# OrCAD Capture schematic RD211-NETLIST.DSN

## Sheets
1 2: size Custom
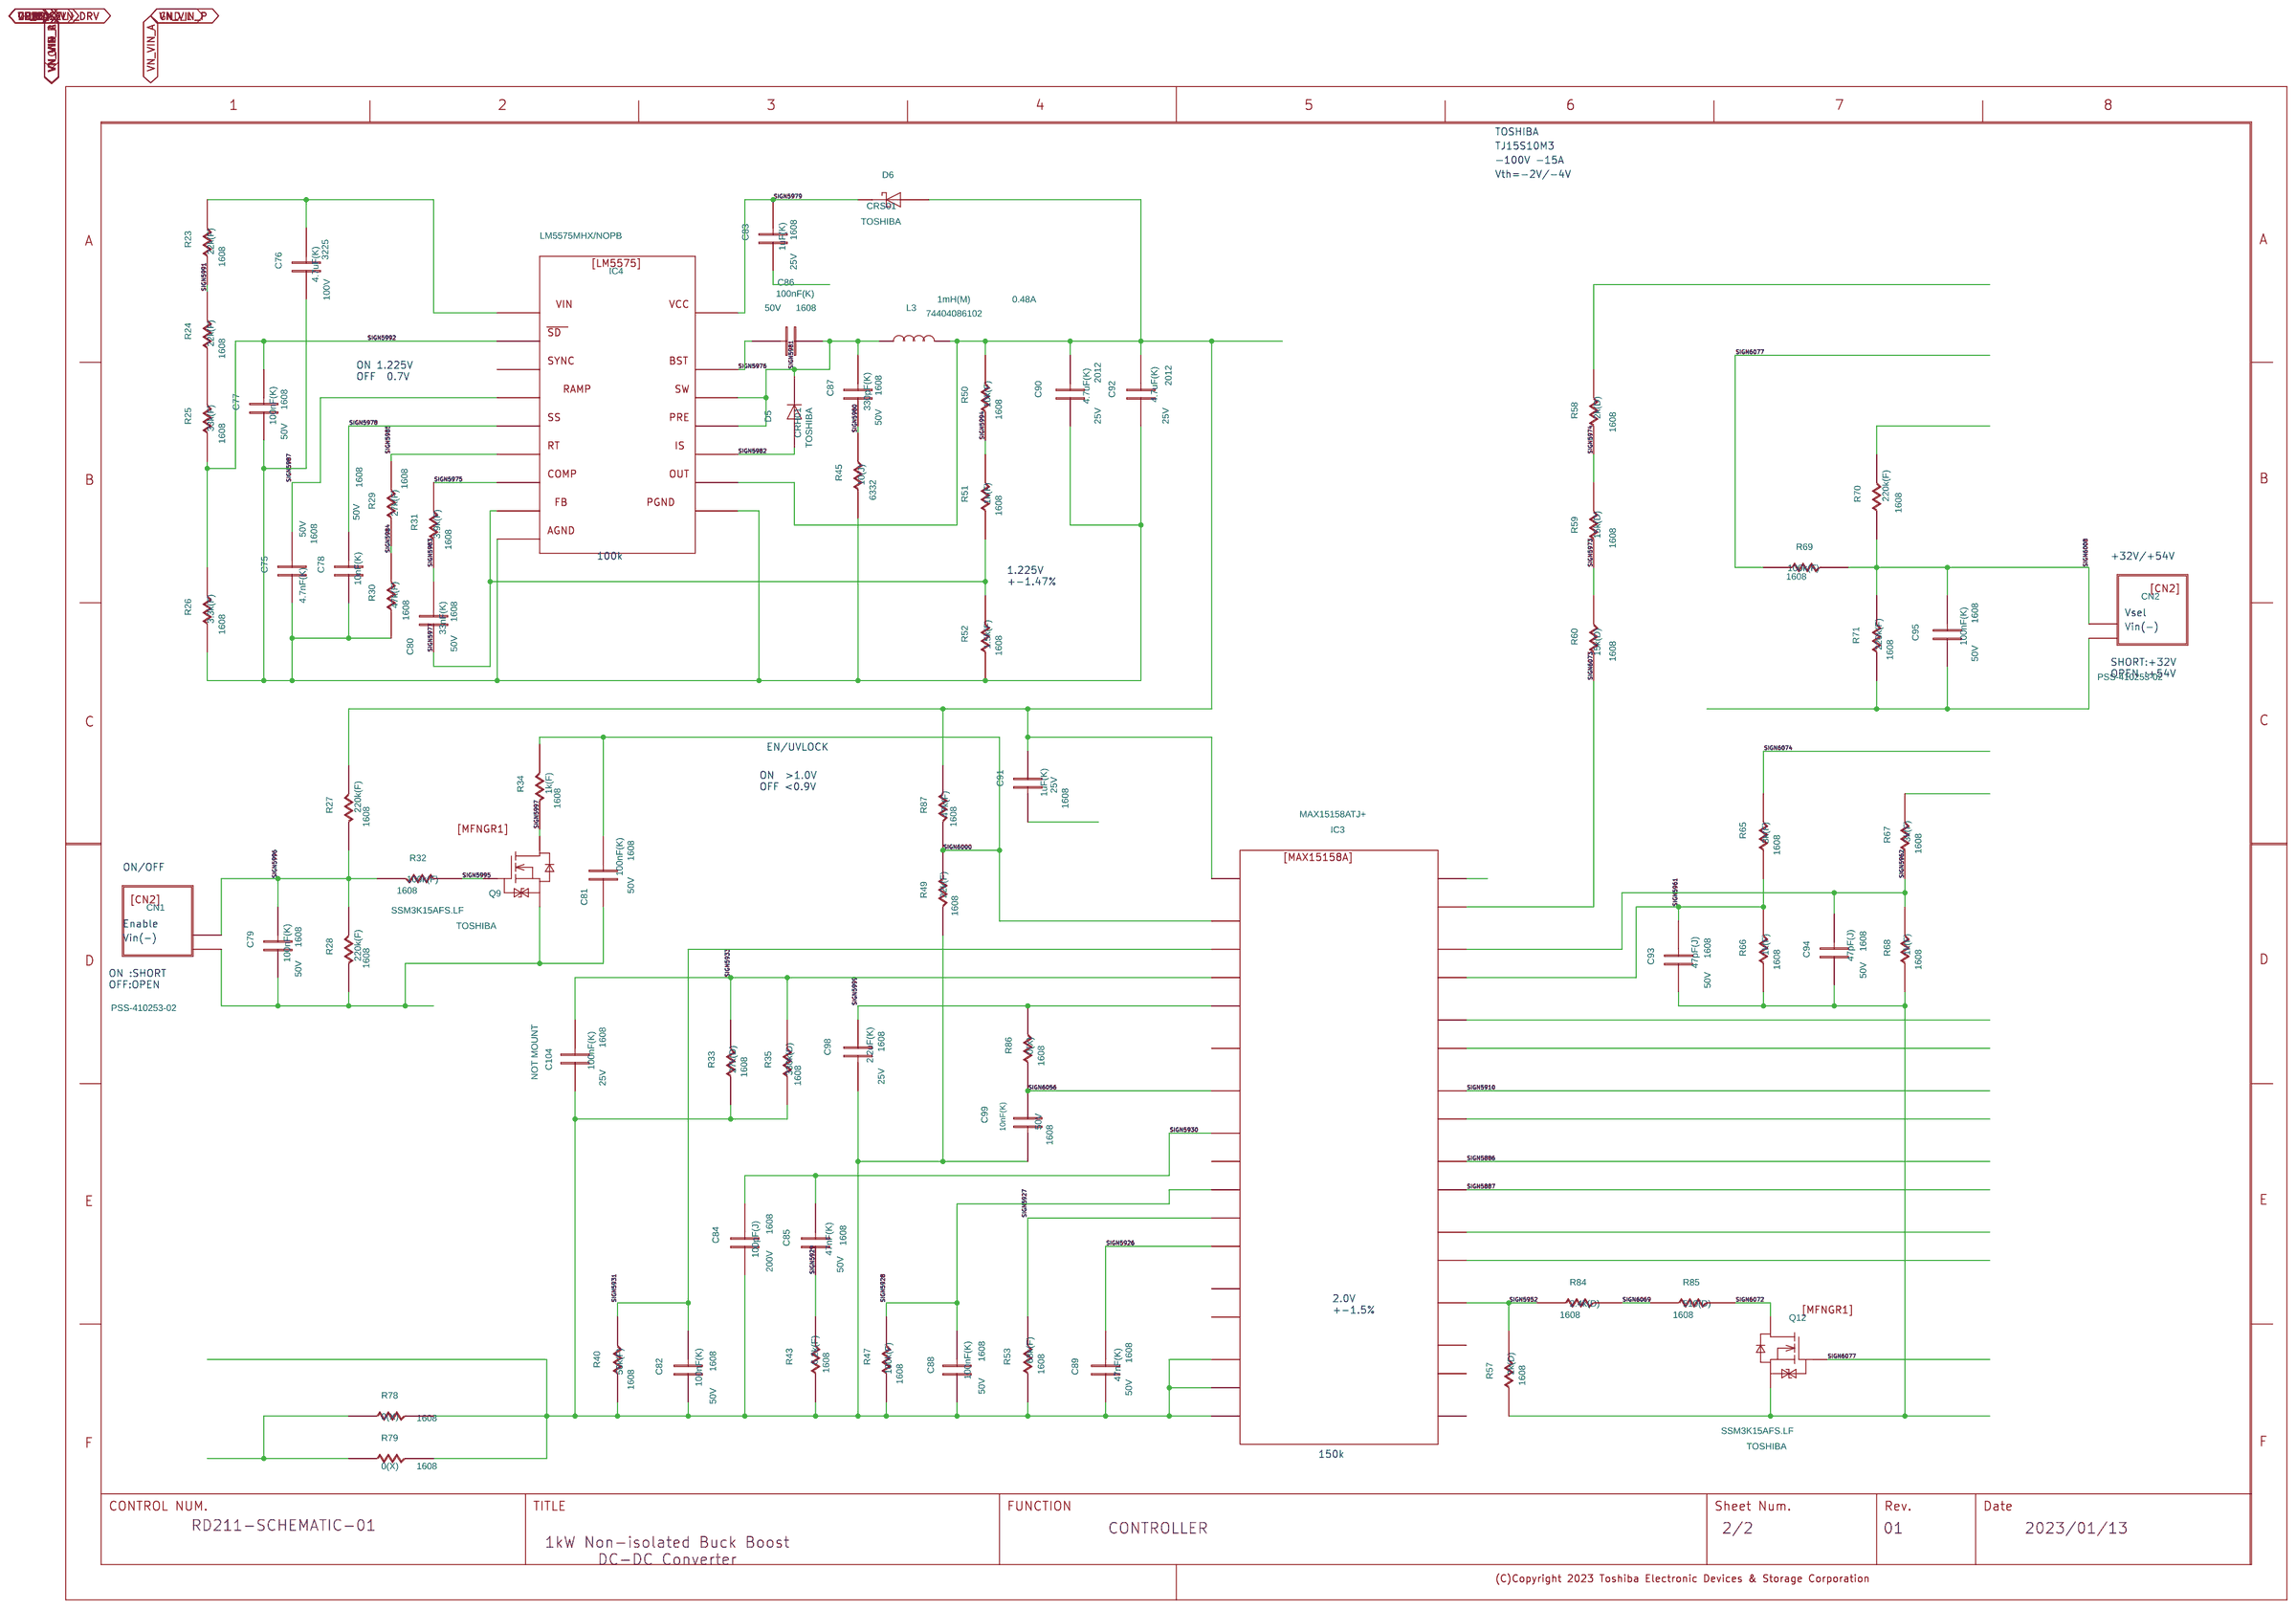
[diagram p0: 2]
2 1: size Custom
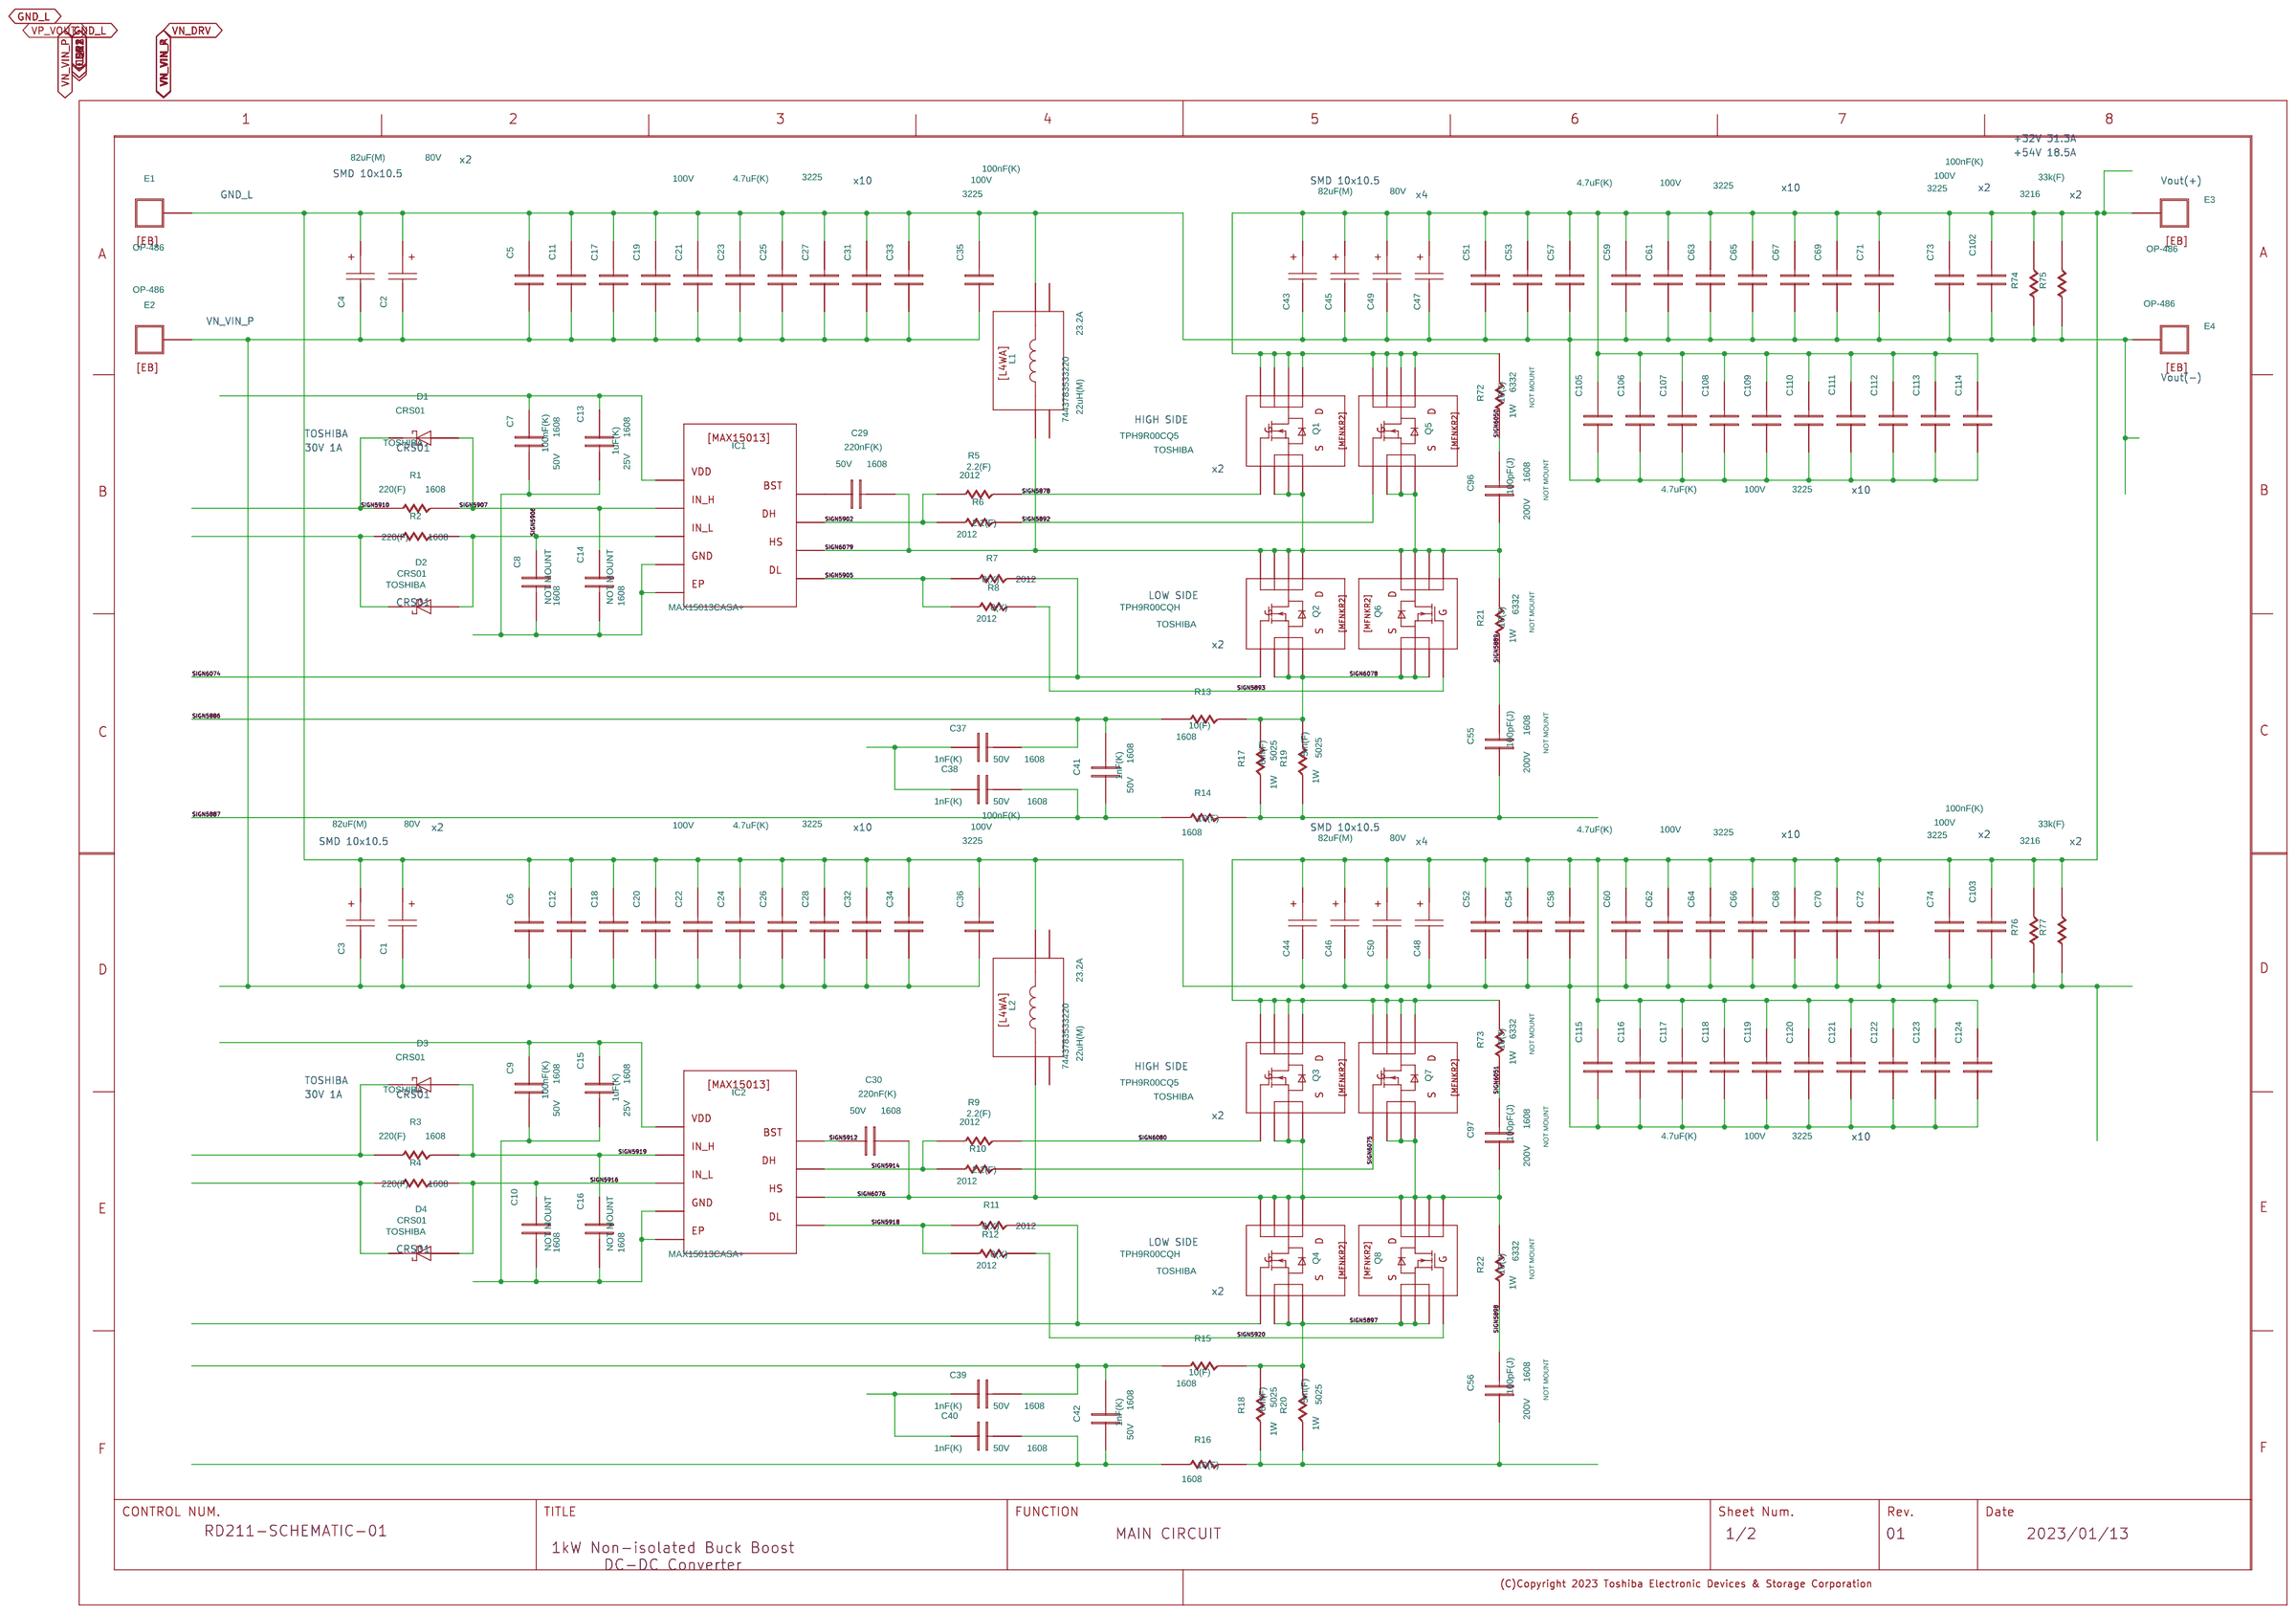
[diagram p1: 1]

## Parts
sheet 1
C1  CP
C2  CP
C3  CP
C4  CP
C5  C
C6  C
C7  C
C8  C
C9  C
C10  C
C11  C
C12  C
C13  C
C14  C
C15  C
C16  C
C17  C
C18  C
C19  C
C20  C
C21  C
C22  C
C23  C
C24  C
C25  C
C26  C
C27  C
C28  C
C29  C
C30  C
C31  C
C32  C
C33  C
C34  C
C35  C
C36  C
C37  C
C38  C
C39  C
C40  C
C41  C
C42  C
C43  CP
C44  CP
C45  CP
C46  CP
C47  CP
C48  CP
C49  CP
C50  CP
C51  C
C52  C
C53  C
C54  C
C55  C
C56  C
C57  C
C58  C
C59  C
C60  C
C61  C
C62  C
C63  C
C64  C
C65  C
C66  C
C67  C
C68  C
C69  C
C70  C
C71  C
C72  C
C73  C
C74  C
C96  C
C97  C
C102  C
C103  C
C105  C
C106  C
C107  C
C108  C
C109  C
C110  C
C111  C
C112  C
C113  C
C114  C
C115  C
C116  C
C117  C
C118  C
C119  C
C120  C
C121  C
C122  C
C123  C
C124  C
D1  SBD
D2  SBD
D3  SBD
D4  SBD
E1  EB
E2  EB
E3  EB
E4  EB
IC1  MAX15013
IC2  MAX15013
L1  L4WA
L2  L4WA
Q1  MFNKR2
Q2  MFNKR2
Q3  MFNKR2
Q4  MFNKR2
Q5  MFNKR2
Q6  MFNKR2
Q7  MFNKR2
Q8  MFNKR2
R1  R
R2  R
R3  R
R4  R
R5  R
R6  R
R7  R
R8  R
R9  R
R10  R
R11  R
R12  R
R13  R
R14  R
R15  R
R16  R
R17  R
R18  R
R19  R
R20  R
R21  R
R22  R
R72  R
R73  R
R74  R
R75  R
R76  R
R77  R
U?#1  WAKU_DEF100
sheet 2
C75  C
C76  C
C77  C
C78  C
C79  C
C80  C
C81  C
C82  C
C83  C
C84  C
C85  C
C86  C
C87  C
C88  C
C89  C
C90  C
C91  C
C92  C
C93  C
C94  C
C95  C
C98  C
C99  C
C104  C
CN1  CN2
CN2  CN2
D5  D
D6  SBD
IC3  MAX15158A
IC4  LM5575
L3  L
Q9  MFNGR1
Q12  MFNGR1
R23  R
R24  R
R25  R
R26  R
R27  R
R28  R
R29  R
R30  R
R31  R
R32  R
R33  R
R34  R
R35  R
R40  R
R43  R
R45  R
R47  R
R49  R
R50  R
R51  R
R52  R
R53  R
R57  R
R58  R
R59  R
R60  R
R65  R
R66  R
R67  R
R68  R
R69  R
R70  R
R71  R
R78  R
R79  R
R84  R
R85  R
R86  R
R87  R
U?#2  WAKU_DEF100

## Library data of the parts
C1-C4 C43-C50 = CP: CAPACITANCETOLE: M; CDMASTERCADCELG: DC845R; COMP: G36030155199; COMPONENTNAME: G36030155199_package; FNCLASSCODEG: P03-01; FNPARTSCODEG: C; FNPARTSNAMEG: CHIP ALUMINUM ELECTROLYTIC CAPACITOR; FUNCN: G36030155199; GCOUNT: 1; ICX_PART_MODEL: CON_470u; MAXGCOUNT: 1; MFFORMINGDIVP: KD; MFMOUNTSYMBOLP: 80; MFPACKAGEMETHOP: S; MFSOLDERINGPROP: F; NOMINALCAPACITA: 470u; OUMECLASSIFICATION: ƒAƒ‹ƒ~“d‰ðƒRƒ“ƒfƒ“ƒT; OUMEMAKER: NAE ¼ºdqi; OUMEMAKERKATAMEI: EEVHB1A471P; OUMEPARTTYPE: C; PCODE: P03090017118; QUADMODEL: CON_470u; RATEDVOLTAGE: 10; SIZECODESMD: 1010; SQ_PART_MODEL: CON_470u; VAL1: 82uF(M); VAL2: 80V
C5 C6 C11 C12 C17-C28 C31-C34 C51-C54 C57-C72 C105-C124 = C: CAPACITANCETOLE: J; CDMASTERCADCELG: C8101B; COMP: G36030013017; COMPONENTNAME: G36030013017_package; FNCLASSCODEG: P03-05; FNPARTSNAMEG: CHIP M-PEN FILM CAPACITOR; FUNCN: G36030013017; GCOUNT: 1; ICX_PART_MODEL: CON_100n; MAXGCOUNT: 1; MFFORMINGDIVP: KC; MFMOUNTSYMBOLP: 80; MFPACKAGEMETHOP: S; MFSOLDERINGPROP: .; NOMINALCAPACITA: 100n; OUMECLASSIFICATION: ƒtƒBƒ‹ƒƒRƒ“ƒfƒ“ƒT; OUMEMAKER: NAT ¼ºdíYÆ; OUMEMAKERKATAMEI: ECWU1C104JB5; PCODE: P03102001111; QUADMODEL: CON_100n; RATEDVOLTAGE: 16; SIZECODESMD: 3225; SQ_PART_MODEL: CON_100n; VAL1: 4.7uF(K); VAL2: 100V
C7 C9 = C: CAPACITANCETOLE: K; CDMASTERCADCELG: KC0008; COMP: GDM030001137; COMPONENTNAME: GDM030001137_package; FNCLASSCODEG: P03-03; FNPARTSNAMEG: CHIP CERAMIC CAPACITOR (1608); FUNCN: GDM030001137; GCOUNT: 1; ICX_PART_MODEL: CON_100n; MAXGCOUNT: 1; MFFORMINGDIVP: KC; MFMOUNTSYMBOLP: 80; MFPACKAGEMETHOP: S; MFSOLDERINGPROP: .; NOMINALCAPACITA: 100n; OUMECLASSIFICATION: ƒZƒ‰ƒ~ƒbƒNƒRƒ“ƒfƒ“ƒT; OUMEMAKER: MRT ºc»ì; OUMEMAKERKATAMEI: GRM188B31H104KA92D; PARTCOMMENT: ã\Z<KC0008> ªtbgvgÉo^³êÄ¢Ü¹ñB; PCODE: P03B000001KW; QUADMODEL: CON_100n; RATEDVOLTAGE: 50; SIZECODESMD: 1608; SQ_PART_MODEL: CON_100n; TEMPCHARACTERI2: B; VAL1: 100nF(K); VAL2: 50V
C8 C10 C14 C16 = C: CAPACITANCETOLE: J; CDMASTERCADCELG: C8100E; COMP: GDM030000578; COMPONENTNAME: GDM030000578_package; FNCLASSCODEG: P03-03; FNPARTSNAMEG: CHIP CERAMIC CAPACITOR (1608); FUNCN: GDM030000578; GCOUNT: 1; ICX_PART_MODEL: CON_220p; MAXGCOUNT: 1; MFFORMINGDIVP: KC; MFMOUNTSYMBOLP: 80; MFPACKAGEMETHOP: S; MFSOLDERINGPROP: .; NOMINALCAPACITA: 220p; NOTMOUNT: NOT MOUNT; OUMECLASSIFICATION: ƒZƒ‰ƒ~ƒbƒNƒRƒ“ƒfƒ“ƒT; OUMEMAKER: KYC ‹žƒZƒ‰; OUMEMAKERKATAMEI: CM105CH221J50AT; PCODE: P03039269127; QUADMODEL: CON_220p; RATEDVOLTAGE: 50; SIZECODESMD: 1608; SQ_PART_MODEL: CON_220p; TEMPCHARACTERI2: CH; VAL1: 220pF(J); VAL2: 50V
C13 C15 C91 = C: CAPACITANCETOLE: K; CDMASTERCADCELG: KC0008; COMP: GDM030000346; COMPONENTNAME: GDM030000346_package; FNCLASSCODEG: P03-03; FNPARTSNAMEG: CHIP CERAMIC CAPACITOR (1608); FUNCN: GDM030000346; GCOUNT: 1; ICX_PART_MODEL: CON_1u; MAXGCOUNT: 1; MFFORMINGDIVP: KC; MFMOUNTSYMBOLP: 80; MFPACKAGEMETHOP: S; MFSOLDERINGPROP: .; NOMINALCAPACITA: 1u; OUMECLASSIFICATION: ƒZƒ‰ƒ~ƒbƒNƒRƒ“ƒfƒ“ƒT; OUMEMAKER: KYC ‹žƒZƒ‰; OUMEMAKERKATAMEI: CV105B105K25AT; PARTCOMMENT: ã\Z<KC0008> ªtbgvgÉo^³êÄ¢Ü¹ñB; PCODE: P03B0000016L; QUADMODEL: CON_1u; RATEDVOLTAGE: 25; SIZECODESMD: 1608; SQ_PART_MODEL: CON_1u; TEMPCHARACTERI2: B; VAL1: 1uF(K); VAL2: 25V
C29 C30 = C: CAPACITANCETOLE: K; CDMASTERCADCELG: KC0008; COMP: GDM030001014; COMPONENTNAME: GDM030001014_package; FNCLASSCODEG: P03-03; FNPARTSNAMEG: CHIP CERAMIC CAPACITOR (1608); FUNCN: GDM030001014; GCOUNT: 1; ICX_PART_MODEL: CON_220n; MAXGCOUNT: 1; MFFORMINGDIVP: KC; MFMOUNTSYMBOLP: 80; MFPACKAGEMETHOP: S; MFSOLDERINGPROP: .; NOMINALCAPACITA: 220n; OUMECLASSIFICATION: ƒZƒ‰ƒ~ƒbƒNƒRƒ“ƒfƒ“ƒT; OUMEMAKER: MRT ºc»ì; OUMEMAKERKATAMEI: GRM188B11C224KA01D; PARTCOMMENT: ã\Z<KC0008> ªtbgvgÉo^³êÄ¢Ü¹ñB; PCODE: P03B000001L3; QUADMODEL: CON_220n; RATEDVOLTAGE: 16; SIZECODESMD: 1608; SQ_PART_MODEL: CON_220n; TEMPCHARACTERI2: B; VAL1: 220nF(K); VAL2: 50V
C35 C36 C73 C74 C102 C103 = C: CAPACITANCETOLE: J; CDMASTERCADCELG: C8101B; COMP: G36030013017; COMPONENTNAME: G36030013017_package; FNCLASSCODEG: P03-05; FNPARTSNAMEG: CHIP M-PEN FILM CAPACITOR; FUNCN: G36030013017; GCOUNT: 1; ICX_PART_MODEL: CON_100n; MAXGCOUNT: 1; MFFORMINGDIVP: KC; MFMOUNTSYMBOLP: 80; MFPACKAGEMETHOP: S; MFSOLDERINGPROP: .; NOMINALCAPACITA: 100n; OUMECLASSIFICATION: ƒtƒBƒ‹ƒƒRƒ“ƒfƒ“ƒT; OUMEMAKER: NAT ¼ºdíYÆ; OUMEMAKERKATAMEI: ECWU1C104JB5; PCODE: P03102001111; QUADMODEL: CON_100n; RATEDVOLTAGE: 16; SIZECODESMD: 3225; SQ_PART_MODEL: CON_100n; VAL1: 100nF(K); VAL2: 100V
C37-C42 = C: ASIMVALUE: 1N; CAPACITANCETOLE: K; CDMASTERCADCELG: C8100E; COMP: G36030011044; COMPONENTNAME: G36030011044_package; FNCLASSCODEG: P03-03; FNPARTSNAMEG: CHIP CERAMIC CAPACITOR (1608); FUNCN: G36030011044; GCOUNT: 1; ICX_PART_MODEL: CON_1n; MAXGCOUNT: 1; MFFORMINGDIVP: KC; MFMOUNTSYMBOLP: 80; MFPACKAGEMETHOP: S; MFSOLDERINGPROP: .; NOMINALCAPACITA: 1n; OUMECLASSIFICATION: ƒZƒ‰ƒ~ƒbƒNƒRƒ“ƒfƒ“ƒT; OUMEMAKER: MRT ºc»ì; OUMEMAKERKATAMEI: GRM39B102K50PT; PCODE: P03039045226; QUADMODEL: CON_1n; RATEDVOLTAGE: 50; SIZECODESMD: 1608; SQ_PART_MODEL: CON_1n; TEMPCHARACTERI2: B; TOLERANCE: K; VAL1: 1nF(K); VAL2: 50V
C55 C56 = C: CAPACITANCETOLE: J; CDMASTERCADCELG: C8100E; COMP: G36030011365; FNCLASSCODEG: P03-03; FNPARTSNAMEG: CHIP CERAMIC CAPACITOR (1608); GCOUNT: 1; MAXGCOUNT: 1; MFFORMINGDIVP: KC; MFMOUNTSYMBOLP: 80; MFPACKAGEMETHOP: S; MFSOLDERINGPROP: .; NOMINALCAPACITA: 100p; NOTMOUNT: NOT MOUNT; OUMECLASSIFICATION: ƒZƒ‰ƒ~ƒbƒNƒRƒ“ƒfƒ“ƒT; OUMEMAKER: KYC ‹žƒZƒ‰; OUMEMAKERKATAMEI: CM105CH101J50AT; PCODE: P03039177125; QUADMODEL: CON_100p; RATEDVOLTAGE: 50; SIZECODESMD: 1608; TEMPCHARACTERI2: CH; TOLERANCE: J; VAL1: 100pF(J); VAL2: 200V
C96 C97 = C: ASIMVALUE: 100P; CAPACITANCETOLE: J; CDMASTERCADCELG: C8100E; COMP: G36030011365; COMPONENTNAME: G36030011365_package; FNCLASSCODEG: P03-03; FNPARTSNAMEG: CHIP CERAMIC CAPACITOR (1608); FUNCN: G36030011365; GCOUNT: 1; ICX_PART_MODEL: CON_100p; MAXGCOUNT: 1; MFFORMINGDIVP: KC; MFMOUNTSYMBOLP: 80; MFPACKAGEMETHOP: S; MFSOLDERINGPROP: .; NOMINALCAPACITA: 100p; NOTMOUNT: NOT MOUNT; OUMECLASSIFICATION: ƒZƒ‰ƒ~ƒbƒNƒRƒ“ƒfƒ“ƒT; OUMEMAKER: KYC ‹žƒZƒ‰; OUMEMAKERKATAMEI: CM105CH101J50AT; PCODE: P03039177125; QUADMODEL: CON_100p; RATEDVOLTAGE: 50; SIZECODESMD: 1608; SQ_PART_MODEL: CON_100p; TEMPCHARACTERI2: CH; TOLERANCE: J; VAL1: 100pF(J); VAL2: 200V
D1-D4 D6 = SBD: CDMASTERCADCELG: DD831R; COMP: G36420146011; COMPONENTNAME: G36420146011_package; FNCLASSCODEG: P42-03; FNPARTSCODEG: D; FNPARTSNAMEG: SCHOTTKY BARRIER DIODE; FORWARDVOLTAGEM: 0; FUNCN: G36420146011; GCOUNT: 1; MAXAVERAGEFORWA: 1; MAXGCOUNT: 1; MAXREPETITIVEPE: 30; MAXREVERSEVOLTA: 0; MFFORMINGDIVP: MM; MFMOUNTSYMBOLP: 80; MFPACKAGEMETHOP: S; MFSOLDERINGPROP: .; MOUNTINGFORMSMD: SMD; OUMECLASSIFICATION: êÊ®¬fq; OUMEMAKER: TSB Åixorrj; OUMEMAKERKATAMEI: CRS01(TE85L); OUMEPARTTYPE: D; PCODE: P42471001117; PEAKFORWARDVOLT: 360m; QUADMODEL: dummymodel; REVERSECURRENT: 0; USERCOMPTEXT3: TOSHIBA; VAL1: CRS01; VAL3: CRS01; ZENERVOLTAGEMAX: 0; ZENERVOLTAGEMIN: 0
E1-E4 = EB: COMP: OP-486; COMPONENTNAME: pinass:EB_func:EB; GCOUNT: 1; MAXGCOUNT: 1; OUMEMAKER: ƒIƒTƒ_; OUMEMAKERKATAMEI: OP-486; VAL1: OP-486; VAL3: OP-486
IC1 IC2 = MAX15013: COMP: MAX15013CASA+; COMPONENTNAME: pinass:MAX15013_func:MAX15013; GCOUNT: 1; MAXGCOUNT: 1; OUMEMAKER: Maxim Integrated; OUMEMAKERKATAMEI: MAX15013CASA+; VAL1: MAX15013CASA+; VAL3: MAX15013CASA+
L1 L2 = L4WA: COMP: 7443783533220; COMPONENTNAME: L4WA.L4WA; GCOUNT: 1; MAXGCOUNT: 1; OUMEMAKER: WURTH; OUMEMAKERKATAMEI: 7443783533330; VAL1: 22uH(M); VAL2: 23.2A; VAL3: 7443783533220
Q1 Q3 Q5 Q7 = MFNKR2: COMP: TPH6R003NL; COMPONENTNAME: MFNKR2_MFNKR2; GCOUNT: 1; MAXGCOUNT: 1; OUMEMAKER: TOSHIBA; OUMEMAKERKATAMEI: TPH6R003NL; USERCOMPTEXT3: TOSHIBA; VAL1: TPH9R00CQ5; VAL3: TPH9R00CQ5
Q2 Q4 = MFNKR2: COMP: TPH6R003NL; COMPONENTNAME: MFNKR2_MFNKR2; GCOUNT: 1; MAXGCOUNT: 1; OUMEMAKER: TOSHIBA; OUMEMAKERKATAMEI: TPH6R003NL; USERCOMPTEXT3: TOSHIBA; VAL1: TPH9R00CQH; VAL3: TPH9R00CQH
Q6 Q8 = MFNKR2: COMP: TPH6R003NL; GCOUNT: 1; MAXGCOUNT: 1; OUMEMAKER: TOSHIBA; OUMEMAKERKATAMEI: TPH6R003NL; USERCOMPTEXT3: TOSHIBA; VAL1: TPH9R00CQH; VAL3: TPH9R00CQH
R1-R4 = R: ASIMVALUE: 220; CDMASTERCADCELG: DR802R; COMP: G36010027393; COMPONENTNAME: G36010027393_package; FNCLASSCODEG: P01-08; FNPARTSNAMEG: CHIP RESISTOR (1608); FUNCN: G36010027393; GCOUNT: 1; ICX_PART_MODEL: RES_220; MAXGCOUNT: 1; MFFORMINGDIVP: KC; MFMOUNTSYMBOLP: 80; MFPACKAGEMETHOP: S; MFSOLDERINGPROP: .; MOUNTINGFORMSMD: SMD; NOMINALRESISTAN: 220; NUMBEROFELEMENT: 0; OUMECLASSIFICATION: \ÊÀpÅèïRí; OUMEMAKER: NAE ¼ºdqi; OUMEMAKERKATAMEI: ERJ3GEYF221V; PCODE: P01042198625; POWERRATING: 63m; QUADMODEL: RES_220; RESISTANCETOLER: F; SIZECODESMD: 1608; SQ_PART_MODEL: RES_220; TOLERANCE: F; VAL1: 220(F); VAL2: 62.5mW
R5 R6 R9 R10 = R: CDMASTERCADCELG: DR910A; COMP: G36010106012; COMPONENTNAME: G36010106012_package; FNCLASSCODEG: P01-08; FNPARTSNAMEG: CHIP RESISTOR (2012); FUNCN: G36010106012; GCOUNT: 1; ICX_PART_MODEL: RES_2.2; MAXGCOUNT: 1; MFFORMINGDIVP: KC; MFMOUNTSYMBOLP: 90; MFPACKAGEMETHOP: S; MFSOLDERINGPROP: .; MOUNTINGFORMSMD: SMD; NOMINALRESISTAN: 2.2; NUMBEROFELEMENT: 0; OUMECLASSIFICATION: \ÊÀpÅèïRí; OUMEMAKER: NAE ¼ºdqi; OUMEMAKERKATAMEI: ERJ6RQF2R2V; PCODE: P01048019214; POWERRATING: 250m; QUADMODEL: RES_2.2; RESISTANCETOLER: F; SIZECODESMD: 2012; SQ_PART_MODEL: RES_2.2; VAL1: 2.2(F); VAL2: 250mW
R7 R8 R11 R12 = R: CDMASTERCADCELG: DR910A; COMP: G36010106081; COMPONENTNAME: G36010106081_package; FNCLASSCODEG: P01-08; FNPARTSNAMEG: CHIP RESISTOR (2012); FUNCN: G36010106081; GCOUNT: 1; ICX_PART_MODEL: RES_1; MAXGCOUNT: 1; MFFORMINGDIVP: KC; MFMOUNTSYMBOLP: 90; MFPACKAGEMETHOP: S; MFSOLDERINGPROP: .; MOUNTINGFORMSMD: SMD; NOMINALRESISTAN: 1; NUMBEROFELEMENT: 0; OUMECLASSIFICATION: \ÊÀpÅèïRí; OUMEMAKER: NAE ¼ºdqi; OUMEMAKERKATAMEI: ERJ6RQF1R0V; PCODE: P01048017210; POWERRATING: 250m; QUADMODEL: RES_1; RESISTANCETOLER: F; SIZECODESMD: 2012; SQ_PART_MODEL: RES_1; VAL1: 0(X)
R13-R16 = R: ASIMVALUE: 10; CDMASTERCADCELG: DR802R; COMP: G36010104063; COMPONENTNAME: G36010104063_package; FNCLASSCODEG: P01-08; FNPARTSNAMEG: CHIP RESISTOR (1608); FUNCN: G36010104063; GCOUNT: 1; ICX_PART_MODEL: RES_10; MAXGCOUNT: 1; MFFORMINGDIVP: KC; MFMOUNTSYMBOLP: 80; MFPACKAGEMETHOP: S; MFSOLDERINGPROP: .; MOUNTINGFORMSMD: SMD; NOMINALRESISTAN: 10; NUMBEROFELEMENT: 0; OUMECLASSIFICATION: \ÊÀpÅèïRí; OUMEMAKER: NAE ¼ºdqi; OUMEMAKERKATAMEI: ERJ3GEYF100V; PCODE: P01042036620; POWERRATING: 63m; QUADMODEL: RES_10; RESISTANCETOLER: F; SIZECODESMD: 1608; SQ_PART_MODEL: RES_10; TOLERANCE: F; VAL1: 10(F); VAL2: 62.5mW
R17 R18 = R: CDMASTERCADCELG: KC0064; COMP: GDM010002006; COMPONENTNAME: GDM010002006_package; FNCLASSCODEG: P01-08; FNPARTSNAMEG: CHIP RESISTOR (5025); FUNCN: GDM010002006; GCOUNT: 1; ICX_PART_MODEL: RES_2m; MAXGCOUNT: 1; MFFORMINGDIVP: KC; MFMOUNTSYMBOLP: 80; MFPACKAGEMETHOP: S; MFSOLDERINGPROP: .; MOUNTINGFORMSMD: SMD; NOMINALRESISTAN: 2m; NUMBEROFELEMENT: 0; OUMECLASSIFICATION: \ÊÀpÅèïRí; OUMEMAKER: KOA ‚j‚n‚`; OUMEMAKERKATAMEI: TLR2HDTE2L00F; PARTCOMMENT: ã\Z<KC0064> ªtbgvgÉo^³êÄ¢Ü¹ñB; PCODE: P01B000002JB; POWERRATING: 1; QUADMODEL: RES_2m; RESISTANCETOLER: F; SIZECODESMD: 5025; SQ_PART_MODEL: RES_2m; VAL1: 6m(F); VAL2: 1W
R19 R20 = R: CDMASTERCADCELG: KC0064; COMP: GDM010002006; COMPONENTNAME: GDM010002006_package; FNCLASSCODEG: P01-08; FNPARTSNAMEG: CHIP RESISTOR (5025); FUNCN: GDM010002006; GCOUNT: 1; ICX_PART_MODEL: RES_2m; MAXGCOUNT: 1; MFFORMINGDIVP: KC; MFMOUNTSYMBOLP: 80; MFPACKAGEMETHOP: S; MFSOLDERINGPROP: .; MOUNTINGFORMSMD: SMD; NOMINALRESISTAN: 2m; NUMBEROFELEMENT: 0; OUMECLASSIFICATION: \ÊÀpÅèïRí; OUMEMAKER: KOA ‚j‚n‚`; OUMEMAKERKATAMEI: TLR2HDTE2L00F; PARTCOMMENT: ã\Z<KC0064> ªtbgvgÉo^³êÄ¢Ü¹ñB; PCODE: P01B000002JB; POWERRATING: 1; QUADMODEL: RES_2m; RESISTANCETOLER: F; SIZECODESMD: 5025; SQ_PART_MODEL: RES_2m; VAL1: 5m(F); VAL2: 1W
R21 R22 = R: CDMASTERCADCELG: R8100A; COMP: 5P9L1082P003; FNCLASSCODEG: P01-08; FNPARTSNAMEG: CHIP RESISTOR (6432); GCOUNT: 1; MAXGCOUNT: 1; MFFORMINGDIVP: KC; MFMOUNTSYMBOLP: 80; MFPACKAGEMETHOP: S; MFSOLDERINGPROP: .; MOUNTINGFORMSMD: SMD; NOMINALRESISTAN: 10; NOTMOUNT: NOT MOUNT; NUMBEROFELEMENT: 0; OUMECLASSIFICATION: \ÊÀpÅèïRí; OUMEMAKER: k¤dCHÆ; OUMEMAKERKATAMEI: CR1 100JE Pb(F); PCODE: P01079008317; POWERRATING: 1; QUADMODEL: RES_10; RESISTANCETOLER: J; SIZECODESMD: 6332; VAL1: 10(J); VAL2: 1W
R72 R73 = R: CDMASTERCADCELG: R8100A; COMP: 5P9L1082P003; COMPONENTNAME: 5P9L1082P003_package; FNCLASSCODEG: P01-08; FNPARTSNAMEG: CHIP RESISTOR (6432); FUNCN: 5P9L1082P003; GCOUNT: 1; ICX_PART_MODEL: RES_10; MAXGCOUNT: 1; MFFORMINGDIVP: KC; MFMOUNTSYMBOLP: 80; MFPACKAGEMETHOP: S; MFSOLDERINGPROP: .; MOUNTINGFORMSMD: SMD; NOMINALRESISTAN: 10; NOTMOUNT: NOT MOUNT; NUMBEROFELEMENT: 0; OUMECLASSIFICATION: \ÊÀpÅèïRí; OUMEMAKER: k¤dCHÆ; OUMEMAKERKATAMEI: CR1 100JE Pb(F); PCODE: P01079008317; POWERRATING: 1; QUADMODEL: RES_10; RESISTANCETOLER: J; SIZECODESMD: 6332; SQ_PART_MODEL: RES_10; VAL1: 10(J); VAL2: 1W
R74-R77 = R: ASIMVALUE: 33K; CDMASTERCADCELG: DR901A; COMP: G36010007395; FNCLASSCODEG: P01-08; FNPARTSNAMEG: CHIP RESISTOR (3216); ICX_PART_MODEL: RES_33K; MFFORMINGDIVP: KC; MFMOUNTSYMBOLP: 90; MFPACKAGEMETHOP: S; MFSOLDERINGPROP: .; MOUNTINGFORMSMD: SMD; NOMINALRESISTAN: 33K; NUMBEROFELEMENT: 0; OUMECLASSIFICATION: \ÊÀpÅèïRí; OUMEMAKER: HDK k¤dCHÆ; OUMEMAKERKATAMEI: CR1/8 333FV; PCODE: P01044453234; POWERRATING: 125m; QUADMODEL: RES_33K; RESISTANCETOLER: F; SIZECODESMD: 3216; SQ_PART_MODEL: RES_33K; TOLERANCE: F; VAL1: 33k(F); VAL2: 250mW
U?#1 = WAKU_DEF100: DATE: 2023/01/13; DRAWINGNUMBER: RD211-SCHEMATIC-01; FUNCTION: MAIN CIRCUIT; REVISION: 01; SAVEAREA0: 22200,72372,612276,319236; SAVECOUNT: 7; SHEETNUMBER: 1/2; TITLE: 1kW Non-isolated Buck Boost / DC-DC Converter; UPDATETIME: 14:13:47
C75 = C: COMP: G36030011280; SIZECODESMD: 1608; VAL1: 4.7nF(K); VAL2: 50V
C76 = C: COMP: G36030013017; SIZECODESMD: 3225; VAL1: 4.7uF(K); VAL2: 100V
C77 C79 = C: COMP: G36030104036; SIZECODESMD: 1608; VAL1: 100nF(K); VAL2: 50V
C78 = C: COMP: G36030011075; SIZECODESMD: 1608; VAL1: 10nF(K); VAL2: 50V
C80 = C: COMP: G510310AM108; SIZECODESMD: 1608; VAL1: 33nF(K); VAL2: 50V
C81 C82 C88 C95 = C: CAPACITANCETOLE: K; CDMASTERCADCELG: C8100E; COMP: G36030104036; COMPONENTNAME: G36030104036_package; FNCLASSCODEG: P03-03; FNPARTSNAMEG: CHIP CERAMIC CAPACITOR (1608); FUNCN: G36030104036; GCOUNT: 1; ICX_PART_MODEL: CON_100n; MAXGCOUNT: 1; MFFORMINGDIVP: KC; MFMOUNTSYMBOLP: 80; MFPACKAGEMETHOP: S; MFSOLDERINGPROP: .; NOMINALCAPACITA: 100n; OUMECLASSIFICATION: ƒZƒ‰ƒ~ƒbƒNƒRƒ“ƒfƒ“ƒT; OUMEMAKER: MRT ºc»ì; OUMEMAKERKATAMEI: GRM39B104K25PT; PCODE: P03039A6F224; QUADMODEL: CON_100n; RATEDVOLTAGE: 25; SIZECODESMD: 1608; SQ_PART_MODEL: CON_100n; TEMPCHARACTERI2: B; VAL1: 100nF(K); VAL2: 50V
C83 = C: COMP: GDM030000346; SIZECODESMD: 1608; VAL1: 1uF(K); VAL2: 25V
C84 = C: ASIMVALUE: 100P; CAPACITANCETOLE: J; CDMASTERCADCELG: C8100E; COMP: G36030011365; COMPONENTNAME: G36030011365_package; FNCLASSCODEG: P03-03; FNPARTSNAMEG: CHIP CERAMIC CAPACITOR (1608); FUNCN: G36030011365; GCOUNT: 1; ICX_PART_MODEL: CON_100p; MAXGCOUNT: 1; MFFORMINGDIVP: KC; MFMOUNTSYMBOLP: 80; MFPACKAGEMETHOP: S; MFSOLDERINGPROP: .; NOMINALCAPACITA: 100p; OUMECLASSIFICATION: ƒZƒ‰ƒ~ƒbƒNƒRƒ“ƒfƒ“ƒT; OUMEMAKER: KYC ‹žƒZƒ‰; OUMEMAKERKATAMEI: CM105CH101J50AT; PCODE: P03039177125; QUADMODEL: CON_100p; RATEDVOLTAGE: 50; SIZECODESMD: 1608; SQ_PART_MODEL: CON_100p; TEMPCHARACTERI2: CH; TOLERANCE: J; VAL1: 100pF(J); VAL2: 200V
C85 C89 = C: ASIMVALUE: 47N; CAPACITANCETOLE: K; CDMASTERCADCELG: C8100E; COMP: G36030011457; COMPONENTNAME: G36030011457_package; FNCLASSCODEG: P03-03; FNPARTSNAMEG: CHIP CERAMIC CAPACITOR (1608); FUNCN: G36030011457; GCOUNT: 1; ICX_PART_MODEL: CON_47n; MAXGCOUNT: 1; MFFORMINGDIVP: KC; MFMOUNTSYMBOLP: 80; MFPACKAGEMETHOP: S; MFSOLDERINGPROP: .; NOMINALCAPACITA: 47n; OUMECLASSIFICATION: ƒZƒ‰ƒ~ƒbƒNƒRƒ“ƒfƒ“ƒT; OUMEMAKER: MRT ºc»ì; OUMEMAKERKATAMEI: GRM39B473K16PT; PCODE: P03039A16226; QUADMODEL: CON_47n; RATEDVOLTAGE: 16; SIZECODESMD: 1608; SQ_PART_MODEL: CON_47n; TEMPCHARACTERI2: B; TOLERANCE: K; VAL1: 47nF(K); VAL2: 50V
C86 = C: COMP: GDM030001005; SIZECODESMD: 1608; VAL1: 100nF(K); VAL2: 50V
C87 = C: COMP: K0300251; SIZECODESMD: 1608; VAL1: 330pF(K); VAL2: 50V
C90 C92 = C: CAPACITANCETOLE: K; CDMASTERCADCELG: DC910A; COMP: G36030029759; COMPONENTNAME: G36030029759_package; FNCLASSCODEG: P03-03; FNPARTSNAMEG: CHIP CERAMIC CAPACITOR (2012); FUNCN: G36030029759; GCOUNT: 1; ICX_PART_MODEL: CON_470n; MAXGCOUNT: 1; MFFORMINGDIVP: KC; MFMOUNTSYMBOLP: 90; MFPACKAGEMETHOP: S; MFSOLDERINGPROP: .; NOMINALCAPACITA: 470n; OUMECLASSIFICATION: ƒZƒ‰ƒ~ƒbƒNƒRƒ“ƒfƒ“ƒT; OUMEMAKER: KYC ‹žƒZƒ‰; OUMEMAKERKATAMEI: CM21B474K25AT; PCODE: P03261001113; QUADMODEL: CON_470n; RATEDVOLTAGE: 25; SIZECODESMD: 2012; SQ_PART_MODEL: CON_470n; TEMPCHARACTERI2: B; VAL1: 4.7uF(K); VAL2: 25V
C93 C94 = C: ASIMVALUE: 47P; CAPACITANCETOLE: J; CDMASTERCADCELG: C8100E; COMP: G36030011150; COMPONENTNAME: G36030011150_package; FNCLASSCODEG: P03-03; FNPARTSNAMEG: CHIP CERAMIC CAPACITOR (1608); FUNCN: G36030011150; GCOUNT: 1; ICX_PART_MODEL: CON_47p; MAXGCOUNT: 1; MFFORMINGDIVP: KC; MFMOUNTSYMBOLP: 80; MFPACKAGEMETHOP: S; MFSOLDERINGPROP: .; NOMINALCAPACITA: 47p; OUMECLASSIFICATION: ƒZƒ‰ƒ~ƒbƒNƒRƒ“ƒfƒ“ƒT; OUMEMAKER: TYD ‘¾—z—U“d; OUMEMAKERKATAMEI: UMK107CH470JZ-T; PCODE: P03039A05626; QUADMODEL: CON_47p; RATEDVOLTAGE: 50; SIZECODESMD: 1608; SQ_PART_MODEL: CON_47p; TEMPCHARACTERI2: CH; TOLERANCE: J; VAL1: 47pF(J); VAL2: 50V
C98 = C: CAPACITANCETOLE: K; CDMASTERCADCELG: KC0008; COMP: GDM030000206; COMPONENTNAME: GDM030000206_package; FNCLASSCODEG: P03-03; FNPARTSNAMEG: CHIP CERAMIC CAPACITOR (1608); FUNCN: GDM030000206; GCOUNT: 1; ICX_PART_MODEL: CON_2.2u; MAXGCOUNT: 1; MFFORMINGDIVP: KC; MFMOUNTSYMBOLP: 80; MFPACKAGEMETHOP: S; MFSOLDERINGPROP: .; NOMINALCAPACITA: 2.2u; OUMECLASSIFICATION: ƒZƒ‰ƒ~ƒbƒNƒRƒ“ƒfƒ“ƒT; OUMEMAKER: MRT ºc»ì; OUMEMAKERKATAMEI: GRM188B10J225KE01D; PARTCOMMENT: ã\Z<KC0008> ªtbgvgÉo^³êÄ¢Ü¹ñB; PCODE: P03B000000ZU; QUADMODEL: CON_2.2u; RATEDVOLTAGE: 6.3; SIZECODESMD: 1608; SQ_PART_MODEL: CON_2.2u; TEMPCHARACTERI2: B; VAL1: 2.2uF(K); VAL2: 25V
C99 = C: ASIMVALUE: 10N; CAPACITANCETOLE: K; CDMASTERCADCELG: C8100E; COMP: G36030011075; COMPONENTNAME: G36030011075_package; FNCLASSCODEG: P03-03; FNPARTSNAMEG: CHIP CERAMIC CAPACITOR (1608); FUNCN: G36030011075; GCOUNT: 1; ICX_PART_MODEL: CON_10n; MAXGCOUNT: 1; MFFORMINGDIVP: KC; MFMOUNTSYMBOLP: 80; MFPACKAGEMETHOP: S; MFSOLDERINGPROP: .; NOMINALCAPACITA: 10n; OUMECLASSIFICATION: ƒZƒ‰ƒ~ƒbƒNƒRƒ“ƒfƒ“ƒT; OUMEMAKER: KYC ‹žƒZƒ‰; OUMEMAKERKATAMEI: CM105W5R103K50AT; PCODE: P03039A11122; QUADMODEL: CON_10n; RATEDVOLTAGE: 50; SIZECODESMD: 1608; SQ_PART_MODEL: CON_10n; TEMPCHARACTERI2: B; TOLERANCE: K; VAL1: 10nF(K); VAL2: 50V
C104 = C: CAPACITANCETOLE: K; CDMASTERCADCELG: C8100E; COMP: G36030104036; COMPONENTNAME: G36030104036_package; FNCLASSCODEG: P03-03; FNPARTSNAMEG: CHIP CERAMIC CAPACITOR (1608); FUNCN: G36030104036; GCOUNT: 1; ICX_PART_MODEL: CON_100n; MAXGCOUNT: 1; MFFORMINGDIVP: KC; MFMOUNTSYMBOLP: 80; MFPACKAGEMETHOP: S; MFSOLDERINGPROP: .; NOMINALCAPACITA: 100n; NOTMOUNT: NOT MOUNT; OUMECLASSIFICATION: ƒZƒ‰ƒ~ƒbƒNƒRƒ“ƒfƒ“ƒT; OUMEMAKER: MRT ºc»ì; OUMEMAKERKATAMEI: GRM39B104K25PT; PCODE: P03039A6F224; QUADMODEL: CON_100n; RATEDVOLTAGE: 25; SIZECODESMD: 1608; SQ_PART_MODEL: CON_100n; TEMPCHARACTERI2: B; VAL1: 100nF(K); VAL2: 25V
CN1 CN2 = CN2: COMP: ZS_DPJ028; OUMEPARTTYPE: PJ; QUADMODEL: dummymodel; VAL1: PSS-410253-02; VAL3: PSS-410253-02
D5 = D: COMP: 5P9L1110P002; COMPONENTNAME: D_D; GCOUNT: 1; MAXGCOUNT: 1; OUMEMAKER: “ŒŽÅ; OUMEMAKERKATAMEI: CMF02(TE12R,Q); SAVEAREA0: -565,-171,12979,8058; SAVECOUNT: 1; USERCOMPTEXT3: TOSHIBA; VAL1: CRH01; VAL3: CRH01
IC3 = MAX15158A: COMP: MAX15158ATJ+; COMPONENTNAME: pinass:MAX15158A_func:MAX15158A; GCOUNT: 1; MAXGCOUNT: 1; OUMEMAKER: Maxim Integrated; OUMEMAKERKATAMEI: MAX15158ATJ+; VAL1: MAX15158ATJ+; VAL3: MAX15158ATJ+
IC4 = LM5575: COMP: LM5575MHX/NOPB; COMPONENTNAME: pinass:LM5575_func:LM5575; GCOUNT: 1; MAXGCOUNT: 1; OUMEMAKER: TI; OUMEMAKERKATAMEI: LM5575MHX/NOPB; VAL1: LM5575MHX/NOPB; VAL3: LM5575MHX/NOPB
L3 = L: COMP: 74404086102; COMPONENTNAME: pinass:L_func:L; GCOUNT: 1; MAXGCOUNT: 1; OUMEMAKER: WURTH; OUMEMAKERKATAMEI: 74404086102; VAL1: 1mH(M); VAL2: 0.48A; VAL3: 74404086102
Q9 Q12 = MFNGR1: CDMASTERCADCELG: DQ815R; COMP: GDM410000111; FNCLASSCODEG: P41-05; FNPARTSCODEG: Q; FNPARTSNAMEG: N-CH MOS FET; MAXCBVOLTAGE: 0; MAXCEVOLTAGE: 0; MAXCOLLECTORCUR: 0; MAXDRAINCURRENT: 100m; MAXDSVOLTAGE: 30; MAXEBVOLTAGE: 0; MAXGATECURRENT: 0; MAXGDVOLTAGE: 0; MAXGSVOLTAGE: 20; MFFORMINGDIVP: MM; MFMOUNTSYMBOLP: 80; MFPACKAGEMETHOP: S; MFSOLDERINGPROP: .; MOUNTINGFORMSMD: SMD; OUMECLASSIFICATION: MOS-FET; OUMEMAKER: TSB Åixorrj; OUMEMAKERKATAMEI: SSM3K15FS(TE85L); OUMEPARTTYPE: Q; PCODE: P41B0000007E; QUADMODEL: dummymodel; USERCOMPTEXT3: TOSHIBA; VAL1: SSM3K15AFS.LF; VAL3: SSM3K15AFS.LF
R23 R24 = R: COMP: G36010027089; SIZECODESMD: 1608; VAL1: 22k(F); VAL2: 62.5mW
R25 = R: COMP: G36010027171; SIZECODESMD: 1608; VAL1: 33k(F); VAL2: 62.5mW
R26 = R: COMP: G36010027027; SIZECODESMD: 1608; VAL1: 3.3k(F); VAL2: 62.5mW
R27 R28 R70 R71 = R: CDMASTERCADCELG: DR802R; COMP: G51011062105; COMPONENTNAME: G51011062105_package; FNCLASSCODEG: P01-08; FNPARTSNAMEG: CHIP RESISTOR (1608); FUNCN: G51011062105; GCOUNT: 1; ICX_PART_MODEL: RES_220K; MAXGCOUNT: 1; MFFORMINGDIVP: KC; MFMOUNTSYMBOLP: 80; MFPACKAGEMETHOP: S; MFSOLDERINGPROP: .; MOUNTINGFORMSMD: SMD; NOMINALRESISTAN: 220K; NUMBEROFELEMENT: 0; OUMECLASSIFICATION: \ÊÀpÅèïRí; OUMEMAKER: NAE ¼ºdqi; OUMEMAKERKATAMEI: ERJ3GEYF224V; PCODE: P01042202629; POWERRATING: 63m; QUADMODEL: RES_220K; RESISTANCETOLER: F; SIZECODESMD: 1608; SQ_PART_MODEL: RES_220K; VAL1: 220k(F); VAL2: 62.5mW
R29 = R: COMP: G36010027195; SIZECODESMD: 1608; VAL1: 27k(F); VAL2: 62.5mW
R30 = R: COMP: G36010027102; SIZECODESMD: 1608; VAL1: 47k(F); VAL2: 62.5mW
R31 = R: COMP: G36010104254; SIZECODESMD: 1608; VAL1: 3.9k(F); VAL2: 62.5mW
R32 R47 R69 = R: ASIMVALUE: 100K; CDMASTERCADCELG: DR802R; COMP: G36010027133; COMPONENTNAME: G36010027133_package; FNCLASSCODEG: P01-08; FNPARTSNAMEG: CHIP RESISTOR (1608); FUNCN: G36010027133; GCOUNT: 1; ICX_PART_MODEL: RES_100K; MAXGCOUNT: 1; MFFORMINGDIVP: KC; MFMOUNTSYMBOLP: 80; MFPACKAGEMETHOP: S; MFSOLDERINGPROP: .; MOUNTINGFORMSMD: SMD; NOMINALRESISTAN: 100K; NUMBEROFELEMENT: 0; OUMECLASSIFICATION: \ÊÀpÅèïRí; OUMEMAKER: HDK k¤dCHÆ; OUMEMAKERKATAMEI: CR1/16 104FV; PCODE: P01042045226; POWERRATING: 63m; QUADMODEL: RES_100K; RESISTANCETOLER: F; SIZECODESMD: 1608; SQ_PART_MODEL: RES_100K; TOLERANCE: F; VAL1: 100k(F); VAL2: 62.5mW
R33 = R: CDMASTERCADCELG: DR802R; COMP: G36010129592; COMPONENTNAME: G36010129592_package; FNCLASSCODEG: P01-08; FNPARTSNAMEG: CHIP RESISTOR (1608); FUNCN: G36010129592; GCOUNT: 1; ICX_PART_MODEL: RES_27K; MAXGCOUNT: 1; MFFORMINGDIVP: KC; MFMOUNTSYMBOLP: 80; MFPACKAGEMETHOP: S; MFSOLDERINGPROP: .; MOUNTINGFORMSMD: SMD; NOMINALRESISTAN: 27K; NUMBEROFELEMENT: 0; OUMECLASSIFICATION: \ÊÀpÅèïRí; OUMEMAKER: KOA ‚j‚n‚`; OUMEMAKERKATAMEI: RK73G1JTD273D; PCODE: P01117063117; POWERRATING: 63m; QUADMODEL: RES_27K; RESISTANCETOLER: D; SIZECODESMD: 1608; SQ_PART_MODEL: RES_27K; VAL1: 27k(D); VAL2: 62.5mW
R34 R51 R66 R68 = R: ASIMVALUE: 1K; CDMASTERCADCELG: DR802R; COMP: G36010027324; COMPONENTNAME: G36010027324_package; FNCLASSCODEG: P01-08; FNPARTSNAMEG: CHIP RESISTOR (1608); FUNCN: G36010027324; GCOUNT: 1; ICX_PART_MODEL: RES_1K; MAXGCOUNT: 1; MFFORMINGDIVP: KC; MFMOUNTSYMBOLP: 80; MFPACKAGEMETHOP: S; MFSOLDERINGPROP: .; MOUNTINGFORMSMD: SMD; NOMINALRESISTAN: 1K; NUMBEROFELEMENT: 0; OUMECLASSIFICATION: \ÊÀpÅèïRí; OUMEMAKER: HDK k¤dCHÆ; OUMEMAKERKATAMEI: CR1/16 102FV; PCODE: P01042521225; POWERRATING: 63m; QUADMODEL: RES_1K; RESISTANCETOLER: F; SIZECODESMD: 1608; SQ_PART_MODEL: RES_1K; TOLERANCE: F; VAL1: 1k(F); VAL2: 62.5mW
R35 = R: CDMASTERCADCELG: DR802R; COMP: G5101109V101; COMPONENTNAME: G5101109V101_package; FNCLASSCODEG: P01-08; FNPARTSNAMEG: CHIP RESISTOR (1608); FUNCN: G5101109V101; GCOUNT: 1; ICX_PART_MODEL: RES_330K; MAXGCOUNT: 1; MFFORMINGDIVP: KC; MFMOUNTSYMBOLP: 80; MFPACKAGEMETHOP: S; MFSOLDERINGPROP: .; MOUNTINGFORMSMD: SMD; NOMINALRESISTAN: 330K; NUMBEROFELEMENT: 0; OUMECLASSIFICATION: \ÊÀpÅèïRí; OUMEMAKER: NAE ¼ºdqi; OUMEMAKERKATAMEI: ERA3YKD334V; PCODE: P01042679629; POWERRATING: 63m; QUADMODEL: RES_330K; RESISTANCETOLER: D; SIZECODESMD: 1608; SQ_PART_MODEL: RES_330K; VAL1: 330k(D); VAL2: 62.5mW
R40 = R: ASIMVALUE: 56K; CDMASTERCADCELG: DR802R; COMP: G36010027119; COMPONENTNAME: G36010027119_package; FNCLASSCODEG: P01-08; FNPARTSNAMEG: CHIP RESISTOR (1608); FUNCN: G36010027119; GCOUNT: 1; ICX_PART_MODEL: RES_56K; MAXGCOUNT: 1; MFFORMINGDIVP: KC; MFMOUNTSYMBOLP: 80; MFPACKAGEMETHOP: S; MFSOLDERINGPROP: .; MOUNTINGFORMSMD: SMD; NOMINALRESISTAN: 56K; NUMBEROFELEMENT: 0; OUMECLASSIFICATION: \ÊÀpÅèïRí; OUMEMAKER: KOA ‚j‚n‚`; OUMEMAKERKATAMEI: RK73H1JTD5602F; PCODE: P01042413421; POWERRATING: 63m; QUADMODEL: RES_56K; RESISTANCETOLER: F; SIZECODESMD: 1608; SQ_PART_MODEL: RES_56K; TOLERANCE: F; VAL1: 56k(F); VAL2: 62.5mW
R43 = R: ASIMVALUE: 6.2K; CDMASTERCADCELG: DR802R; COMP: G36010027379; COMPONENTNAME: G36010027379_package; FNCLASSCODEG: P01-08; FNPARTSNAMEG: CHIP RESISTOR (1608); FUNCN: G36010027379; GCOUNT: 1; ICX_PART_MODEL: RES_6.2K; MAXGCOUNT: 1; MFFORMINGDIVP: KC; MFMOUNTSYMBOLP: 80; MFPACKAGEMETHOP: S; MFSOLDERINGPROP: .; MOUNTINGFORMSMD: SMD; NOMINALRESISTAN: 6.2K; NUMBEROFELEMENT: 0; OUMECLASSIFICATION: \ÊÀpÅèïRí; OUMEMAKER: KOA ‚j‚n‚`; OUMEMAKERKATAMEI: RK73H1JTD6201F; PCODE: P01042419423; POWERRATING: 63m; QUADMODEL: RES_6.2K; RESISTANCETOLER: F; SIZECODESMD: 1608; SQ_PART_MODEL: RES_6.2K; TOLERANCE: F; VAL1: 6.2k(F); VAL2: 62.5mW
R45 = R: COMP: 5P9L1082P003; SIZECODESMD: 6332; VAL1: 10(J); VAL2: 1W
R49 = R: ASIMVALUE: 22K; CDMASTERCADCELG: DR802R; COMP: G36010027089; COMPONENTNAME: G36010027089_package; FNCLASSCODEG: P01-08; FNPARTSNAMEG: CHIP RESISTOR (1608); FUNCN: G36010027089; GCOUNT: 1; ICX_PART_MODEL: RES_22K; MAXGCOUNT: 1; MFFORMINGDIVP: KC; MFMOUNTSYMBOLP: 80; MFPACKAGEMETHOP: S; MFSOLDERINGPROP: .; MOUNTINGFORMSMD: SMD; NOMINALRESISTAN: 22K; NUMBEROFELEMENT: 0; OUMECLASSIFICATION: \ÊÀpÅèïRí; OUMEMAKER: KOA ‚j‚n‚`; OUMEMAKERKATAMEI: RK73H1JTD2202F; PCODE: P01042207426; POWERRATING: 63m; QUADMODEL: RES_22K; RESISTANCETOLER: F; SIZECODESMD: 1608; SQ_PART_MODEL: RES_22K; TOLERANCE: F; VAL1: 22k(F); VAL2: 62.5mW
R50 = R: ASIMVALUE: 10K; CDMASTERCADCELG: DR802R; COMP: G36010027034; COMPONENTNAME: G36010027034_package; FNCLASSCODEG: P01-08; FNPARTSNAMEG: CHIP RESISTOR (1608); FUNCN: G36010027034; GCOUNT: 1; ICX_PART_MODEL: RES_10K; MAXGCOUNT: 1; MFFORMINGDIVP: KC; MFMOUNTSYMBOLP: 80; MFPACKAGEMETHOP: S; MFSOLDERINGPROP: .; MOUNTINGFORMSMD: SMD; NOMINALRESISTAN: 10K; NUMBEROFELEMENT: 0; OUMECLASSIFICATION: \ÊÀpÅèïRí; OUMEMAKER: SAM O¯d@; OUMEMAKERKATAMEI: RC1608F103CS; PCODE: P01042049A26; POWERRATING: 63m; QUADMODEL: RES_10K; RESISTANCETOLER: F; SIZECODESMD: 1608; SQ_PART_MODEL: RES_10K; TOLERANCE: F; VAL1: 10k(F); VAL2: 62.5mW
R52 = R: ASIMVALUE: 1.5K; CDMASTERCADCELG: DR802R; COMP: G36010027232; COMPONENTNAME: G36010027232_package; FNCLASSCODEG: P01-08; FNPARTSNAMEG: CHIP RESISTOR (1608); FUNCN: G36010027232; GCOUNT: 1; ICX_PART_MODEL: RES_1.5K; MAXGCOUNT: 1; MFFORMINGDIVP: KC; MFMOUNTSYMBOLP: 80; MFPACKAGEMETHOP: S; MFSOLDERINGPROP: .; MOUNTINGFORMSMD: SMD; NOMINALRESISTAN: 1.5K; NUMBEROFELEMENT: 0; OUMECLASSIFICATION: \ÊÀpÅèïRí; OUMEMAKER: HDK k¤dCHÆ; OUMEMAKERKATAMEI: CR1/16 152FV; PCODE: P01042512223; POWERRATING: 63m; QUADMODEL: RES_1.5K; RESISTANCETOLER: F; SIZECODESMD: 1608; SQ_PART_MODEL: RES_1.5K; TOLERANCE: F; VAL1: 1.5k(F); VAL2: 62.5mW
R53 = R: ASIMVALUE: 68K; CDMASTERCADCELG: DR802R; COMP: G36010027126; COMPONENTNAME: G36010027126_package; FNCLASSCODEG: P01-08; FNPARTSNAMEG: CHIP RESISTOR (1608); FUNCN: G36010027126; GCOUNT: 1; ICX_PART_MODEL: RES_68K; MAXGCOUNT: 1; MFFORMINGDIVP: KC; MFMOUNTSYMBOLP: 80; MFPACKAGEMETHOP: S; MFSOLDERINGPROP: .; MOUNTINGFORMSMD: SMD; NOMINALRESISTAN: 68K; NUMBEROFELEMENT: 0; OUMECLASSIFICATION: \ÊÀpÅèïRí; OUMEMAKER: HDK k¤dCHÆ; OUMEMAKERKATAMEI: CR1/16 683FV; PCODE: P01042456220; POWERRATING: 63m; QUADMODEL: RES_68K; RESISTANCETOLER: F; SIZECODESMD: 1608; SQ_PART_MODEL: RES_68K; TOLERANCE: F; VAL1: 68k(F); VAL2: 62.5mW
R57 = R: CDMASTERCADCELG: DR802R; COMP: G36010129325; COMPONENTNAME: G36010129325_package; FNCLASSCODEG: P01-08; FNPARTSNAMEG: CHIP RESISTOR (1608); FUNCN: G36010129325; GCOUNT: 1; ICX_PART_MODEL: RES_2K; MAXGCOUNT: 1; MFFORMINGDIVP: KC; MFMOUNTSYMBOLP: 80; MFPACKAGEMETHOP: S; MFSOLDERINGPROP: .; MOUNTINGFORMSMD: SMD; NOMINALRESISTAN: 2K; NUMBEROFELEMENT: 0; OUMECLASSIFICATION: \ÊÀpÅèïRí; OUMEMAKER: KOA ‚j‚n‚`; OUMEMAKERKATAMEI: RK73G1JTD202D; PCODE: P01117036111; POWERRATING: 63m; QUADMODEL: RES_2K; RESISTANCETOLER: D; SIZECODESMD: 1608; SQ_PART_MODEL: RES_2K; VAL1: 2k(D); VAL2: 62.5mW
R58 = R: CDMASTERCADCELG: DR802R; COMP: G36010014317; COMPONENTNAME: G36010014317_package; FNCLASSCODEG: P01-08; FNPARTSNAMEG: CHIP RESISTOR (1608); FUNCN: G36010014317; GCOUNT: 1; ICX_PART_MODEL: RES_2K; MAXGCOUNT: 1; MFFORMINGDIVP: KC; MFMOUNTSYMBOLP: 80; MFPACKAGEMETHOP: S; MFSOLDERINGPROP: .; MOUNTINGFORMSMD: SMD; NOMINALRESISTAN: 2K; NUMBEROFELEMENT: 0; OUMECLASSIFICATION: \ÊÀpÅèïRí; OUMEMAKER: NAE ¼ºdqi; OUMEMAKERKATAMEI: ERA3YED202V; PCODE: P01042549625; POWERRATING: 63m; QUADMODEL: RES_2K; RESISTANCETOLER: D; SIZECODESMD: 1608; SQ_PART_MODEL: RES_2K; VAL1: 2k(D); VAL2: 62.5mW
R59 R60 = R: CDMASTERCADCELG: DR802R; COMP: G36010014225; COMPONENTNAME: G36010014225_package; FNCLASSCODEG: P01-08; FNPARTSNAMEG: CHIP RESISTOR (1608); FUNCN: G36010014225; GCOUNT: 1; ICX_PART_MODEL: RES_15K; MAXGCOUNT: 1; MFFORMINGDIVP: KC; MFMOUNTSYMBOLP: 80; MFPACKAGEMETHOP: S; MFSOLDERINGPROP: .; MOUNTINGFORMSMD: SMD; NOMINALRESISTAN: 15K; NUMBEROFELEMENT: 0; OUMECLASSIFICATION: \ÊÀpÅèïRí; OUMEMAKER: NAE ¼ºdqi; OUMEMAKERKATAMEI: ERA3YED153V; PCODE: P01042541629; POWERRATING: 63m; QUADMODEL: RES_15K; RESISTANCETOLER: D; SIZECODESMD: 1608; SQ_PART_MODEL: RES_15K; VAL1: 15k(D); VAL2: 62.5mW
R65 R67 = R: CDMASTERCADCELG: DR802R; COMP: G36010104377; COMPONENTNAME: G36010104377_package; FNCLASSCODEG: P01-08; FNPARTSNAMEG: CHIP RESISTOR (1608); FUNCN: G36010104377; GCOUNT: 1; ICX_PART_MODEL: RES_3K; MAXGCOUNT: 1; MFFORMINGDIVP: KC; MFMOUNTSYMBOLP: 80; MFPACKAGEMETHOP: S; MFSOLDERINGPROP: .; MOUNTINGFORMSMD: SMD; NOMINALRESISTAN: 3K; NUMBEROFELEMENT: 0; OUMECLASSIFICATION: \ÊÀpÅèïRí; OUMEMAKER: KOA ‚j‚n‚`; OUMEMAKERKATAMEI: RK73H1JTD3001F; PCODE: P01042331428; POWERRATING: 63m; QUADMODEL: RES_3K; RESISTANCETOLER: F; SIZECODESMD: 1608; SQ_PART_MODEL: RES_3K; VAL1: 3k(F); VAL2: 62.5mW
R78 R79 R86 = R: CDMASTERCADCELG: KC0008; COMP: G8800256207A; COMPONENTNAME: G8800256207A_package; FNCLASSCODEG: P01-08; FNPARTSNAMEG: RESISTOR; FUNCN: G8800256207A; GCOUNT: 1; ICX_PART_MODEL: RES_0; MAXGCOUNT: 1; MFFORMINGDIVP: KC; MFMOUNTSYMBOLP: 80; MFPACKAGEMETHOP: S; MFSOLDERINGPROP: .; MOUNTINGFORMSMD: SMD; NOMINALRESISTAN: 0; NUMBEROFELEMENT: 0; OUMECLASSIFICATION: \ÊÀpÅèïRí; OUMEMAKER: NAE ¼ºdqi; OUMEMAKERKATAMEI: ERJ3GEY0R00V; PARTCOMMENT: ã\Z<KC0008> ªtbgvgÉo^³êÄ¢Ü¹ñB; PCODE: P01042608629; POWERRATING: 63m; QUADMODEL: RES_0; RESISTANCETOLER: X; SIZECODESMD: 1608; SQ_PART_MODEL: RES_0; VAL1: 0(X)
R84 = R: CDMASTERCADCELG: DR802R; COMP: G36010014386; COMPONENTNAME: G36010014386_package; FNCLASSCODEG: P01-08; FNPARTSNAMEG: CHIP RESISTOR (1608); FUNCN: G36010014386; GCOUNT: 1; ICX_PART_MODEL: RES_2.4K; MAXGCOUNT: 1; MFFORMINGDIVP: KC; MFMOUNTSYMBOLP: 80; MFPACKAGEMETHOP: S; MFSOLDERINGPROP: .; MOUNTINGFORMSMD: SMD; NOMINALRESISTAN: 2.4K; NUMBEROFELEMENT: 0; OUMECLASSIFICATION: \ÊÀpÅèïRí; OUMEMAKER: NAE ¼ºdqi; OUMEMAKERKATAMEI: ERA3YED242V; PCODE: P01042554629; POWERRATING: 63m; QUADMODEL: RES_2.4K; RESISTANCETOLER: D; SIZECODESMD: 1608; SQ_PART_MODEL: RES_2.4K; VAL1: 2.4k(D); VAL2: 62.5mW
R85 = R: CDMASTERCADCELG: DR802R; COMP: G36010014621; COMPONENTNAME: G36010014621_package; FNCLASSCODEG: P01-08; FNPARTSNAMEG: CHIP RESISTOR (1608); FUNCN: G36010014621; GCOUNT: 1; ICX_PART_MODEL: RES_510; MAXGCOUNT: 1; MFFORMINGDIVP: KC; MFMOUNTSYMBOLP: 80; MFPACKAGEMETHOP: S; MFSOLDERINGPROP: .; MOUNTINGFORMSMD: SMD; NOMINALRESISTAN: 510; NUMBEROFELEMENT: 0; OUMECLASSIFICATION: \ÊÀpÅèïRí; OUMEMAKER: NAE ¼ºdqi; OUMEMAKERKATAMEI: ERA3YED511V; PCODE: P01042570629; POWERRATING: 63m; QUADMODEL: RES_510; RESISTANCETOLER: D; SIZECODESMD: 1608; SQ_PART_MODEL: RES_510; VAL1: 510(D); VAL2: 62.5mW
R87 = R: ASIMVALUE: 47K; CDMASTERCADCELG: DR802R; COMP: G36010027102; COMPONENTNAME: G36010027102_package; FNCLASSCODEG: P01-08; FNPARTSNAMEG: CHIP RESISTOR (1608); FUNCN: G36010027102; GCOUNT: 1; ICX_PART_MODEL: RES_47K; MAXGCOUNT: 1; MFFORMINGDIVP: KC; MFMOUNTSYMBOLP: 80; MFPACKAGEMETHOP: S; MFSOLDERINGPROP: .; MOUNTINGFORMSMD: SMD; NOMINALRESISTAN: 47K; NUMBEROFELEMENT: 0; OUMECLASSIFICATION: \ÊÀpÅèïRí; OUMEMAKER: KOA ‚j‚n‚`; OUMEMAKERKATAMEI: RK73H1JTD4702F; PCODE: P01042373428; POWERRATING: 63m; QUADMODEL: RES_47K; RESISTANCETOLER: F; SIZECODESMD: 1608; SQ_PART_MODEL: RES_47K; TOLERANCE: F; VAL1: 47k(F); VAL2: 62.5mW
U?#2 = WAKU_DEF100: DATE: 2023/01/13; DRAWINGNUMBER: RD211-SCHEMATIC-01; FUNCTION: CONTROLLER; REVISION: 01; SAVEAREA0: 22200,72372,612276,319236; SAVECOUNT: 7; SHEETNUMBER: 2/2; TITLE: 1kW Non-isolated Buck Boost / DC-DC Converter; UPDATETIME: 14:14:23

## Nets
GND_L: C1.2 C2.2 C3.2 C4.2 C5.2 C6.2 C11.2 C12.2 C17.2 C18.2 C19.2 C20.2 C21.2 C22.2 C23.2 C24.2 C25.2 C26.2 C27.2 C28.2 C31.2 C32.2 C33.2 C34.2 C35.2 C36.2 C43.1 C44.1 C45.1 C46.1 C47.1 C48.1 C49.1 C50.1 C51.1 C52.1 C53.1 C54.1 C57.1 C58.1 C59.1 C60.1 C61.1 C62.1 C63.1 C64.1 C65.1 C66.1 C67.1 C68.1 C69.1 C70.1 C71.1 C72.1 C73.1 C74.1 C76.2 C102.1 C103.1 C105.1 C106.1 C107.1 C108.1 C109.1 C110.1 C111.1 C112.1 C113.1 C114.1 C115.1 C116.1 C117.1 C118.1 C119.1 C120.1 C121.1 C122.1 C123.1 C124.1 E1.1 E4.1 IC3.18 IC4.3 L1.4 L2.4 R23.2 R74.1 R75.1 R76.1 R77.1
CSN1: C38.2 C41.1 IC3.29 R14.1
CSN2: C40.2 C42.1 IC3.30 R16.1
CSP1: C37.2 C41.2 IC3.28 R13.1
CSP2: C39.2 C42.2 IC3.31 R15.1
DH1: D1.C IC3.27 R1.1
DH2: D3.C IC3.2 R3.1
DL1: D2.C IC3.26 R2.1
DL2: D4.C IC3.1 R4.1
DL_1A: Q2.4 R7.2 R65.2
DL_2A: Q4.4 R11.2 R67.2
SIGN5878: Q1.4 R5.2
SIGN5889: C55.2 R21.1
SIGN5892: Q5.4 R6.2
SIGN5893: Q6.4 R8.2
SIGN5897: Q4.1 Q4.2 Q4.3 Q8.1 Q8.2 Q8.3 R15.2 R18.1 R20.1
SIGN5898: C56.2 R22.1
SIGN5902: IC1.3 R5.1 R6.1
SIGN5905: IC1.8 R7.1 R8.1
SIGN5906: C8.1 D2.A IC1.6 R2.2
SIGN5907: C14.1 D1.A IC1.5 R1.2
SIGN5912: C30.1 IC2.2
SIGN5914: IC2.3 R9.1 R10.1
SIGN5916: C10.1 D4.A IC2.6 R4.2
SIGN5918: IC2.8 R11.1 R12.1
SIGN5919: C16.1 D3.A IC2.5 R3.2
SIGN5920: Q8.4 R12.2
SIGN5926: C89.2 IC3.12
SIGN5927: IC3.11 R53.2
SIGN5928: C88.2 IC3.10 R47.2
SIGN5929: C85.1 R43.2
SIGN5930: C84.2 C85.2 IC3.13
SIGN5931: C82.2 IC3.9 R40.2
SIGN5933: C104.2 IC3.4 R33.2 R35.2
SIGN5952: IC3.14 R57.2 R84.1
SIGN5961: C93.2 IC3.25 R65.1 R66.2
SIGN5962: C94.2 IC3.32 R67.1 R68.2
SIGN5973: R59.1 R60.2
SIGN5974: R58.1 R59.2
SIGN5975: IC4.5 R31.2
SIGN5976: C86.2 IC4.16
SIGN5977: C80.1 IC4.6 R51.1 R52.2
SIGN5978: C78.2 IC4.10
SIGN5979: C83.2 D6.C IC4.1
SIGN5980: C87.1 R45.2
SIGN5981: C86.1 C87.2 D5.C IC4.14 IC4.15 L3.1
SIGN5982: D5.A IC4.13
SIGN5983: C80.2 R31.1
SIGN5984: R29.1 R30.2
SIGN5985: IC4.7 R29.2
SIGN5987: C75.2 IC4.8
SIGN5991: R23.1 R24.2
SIGN5992: C77.2 IC4.2 R25.1 R26.2
SIGN5994: R50.1 R51.2
SIGN5995: Q9.G R32.1
SIGN5996: C79.2 CN1.1 R27.1 R28.2 R32.2
SIGN5997: Q9.D R34.1
SIGN5999: C98.1 IC3.21 R86.2
SIGN6000: C81.2 IC3.22 R34.2 R49.1 R87.2
SIGN6008: C95.2 CN2.1 R69.2 R70.1 R71.2
SIGN6050: C96.2 R72.1
SIGN6051: C97.2 R73.1
SIGN6056: C99.1 IC3.15 R86.1
SIGN6069: R84.2 R85.1
SIGN6072: Q12.D R85.2
SIGN6073: IC3.17 R60.1
SIGN6075: Q7.4 R10.2
SIGN6076: C30.2 C97.1 IC2.4 L2.1 Q3.1 Q3.2 Q3.3 Q4.5 Q4.6 Q4.7 Q4.8 Q7.1 Q7.2 Q7.3 Q8.5 Q8.6 Q8.7 Q8.8 R22.2
SIGN6078: Q2.1 Q2.2 Q2.3 Q6.1 Q6.2 Q6.3 R13.2 R17.1 R19.1
SIGN6079: C29.2 C96.1 IC1.4 L1.1 Q1.1 Q1.2 Q1.3 Q2.5 Q2.6 Q2.7 Q2.8 Q5.1 Q5.2 Q5.3 Q6.5 Q6.6 Q6.7 Q6.8 R21.2
SIGN6080: Q3.4 R9.2
VN_DRV: C7.1 C9.1 C13.1 C15.1 C90.2 C91.1 C92.2 D6.A IC1.1 IC2.1 IC3.24 IC4.11 L3.2 R27.2 R50.2 R70.2 R87.1
VN_VIN_A: C37.1 C38.1 C39.1 C40.1 C79.1 C81.1 C82.1 C84.1 C88.1 C89.1 C91.2 C93.1 C94.1 C95.1 C98.2 C99.2 C104.1 CN1.2 CN2.2 IC3.5 IC3.23 IC3.33 Q9.S Q12.S R28.1 R33.1 R35.1 R40.1 R43.1 R47.1 R49.2 R53.1 R57.1 R66.1 R68.1 R71.1 R78.2 R79.2
VN_VIN_P: C1.1 C2.1 C3.1 C4.1 C5.1 C6.1 C7.2 C8.2 C9.2 C10.2 C11.1 C12.1 C13.2 C14.2 C15.2 C16.2 C17.1 C18.1 C19.1 C20.1 C21.1 C22.1 C23.1 C24.1 C25.1 C26.1 C27.1 C28.1 C31.1 C32.1 C33.1 C34.1 C35.1 C36.1 C55.1 C56.1 C75.1 C76.1 C77.1 C78.1 C83.1 C90.1 C92.1 E2.1 IC1.7 IC1.9 IC2.7 IC2.9 IC4.9 IC4.12 R14.2 R16.2 R17.2 R18.2 R19.2 R20.2 R26.1 R30.1 R45.1 R52.1 R78.1 R79.1
VP_VOUT: C43.2 C44.2 C45.2 C46.2 C47.2 C48.2 C49.2 C50.2 C51.2 C52.2 C53.2 C54.2 C57.2 C58.2 C59.2 C60.2 C61.2 C62.2 C63.2 C64.2 C65.2 C66.2 C67.2 C68.2 C69.2 C70.2 C71.2 C72.2 C73.2 C74.2 C102.2 C103.2 C105.2 C106.2 C107.2 C108.2 C109.2 C110.2 C111.2 C112.2 C113.2 C114.2 C115.2 C116.2 C117.2 C118.2 C119.2 C120.2 C121.2 C122.2 C123.2 C124.2 E3.1 Q1.5 Q1.6 Q1.7 Q1.8 Q3.5 Q3.6 Q3.7 Q3.8 Q5.5 Q5.6 Q5.7 Q5.8 Q7.5 Q7.6 Q7.7 Q7.8 R58.2 R72.2 R73.2 R74.2 R75.2 R76.2 R77.2
VREF_SEL: Q12.G R69.1
N03931: C29.1 IC1.2
N06331: R24.1 R25.2

Not connected (* = marked no-connect by the designer): IC3 3 6 7 8 16 19 20; IC4 4; L1 2 3; L2 2 3

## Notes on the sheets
sheet 1
- TOSHIBA
- TJ15S10M3
- -100V -15A
- Vth=-2V/-4V
- ON 1.225V
  OFF  0.7V
- 100k
- +32V/+54V
- 1.225V
  +-1.47%
- Vsel
- Vin(-)
- SHORT:+32V
  OPEN :+54V
- EN/UVLOCK
- ON  >1.0V
  OFF <0.9V
- ON/OFF
- Enable
- Vin(-)
- ON :SHORT
  OFF:OPEN
- 2.0V
  +-1.5%
- 150k
sheet 2
- +32V 31.3A
- x2
- +54V 18.5A
- SMD 10x10.5
- GND_L
- x10
- SMD 10x10.5
- x4
- x10
- x2
- x2
- Vout(+)
- VN_VIN_P
- Vout(-)
- HIGH SIDE
- TOSHIBA
- 30V 1A
- CRS01
- x2
- x10
- LOW SIDE
- CRS01
- x2
- x2
- x10
- SMD 10x10.5
- SMD 10x10.5
- x4
- x10
- x2
- x2
- HIGH SIDE
- TOSHIBA
- 30V 1A
- CRS01
- x2
- x10
- LOW SIDE
- CRS01
- x2
